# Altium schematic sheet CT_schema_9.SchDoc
size 278 x 170 mm
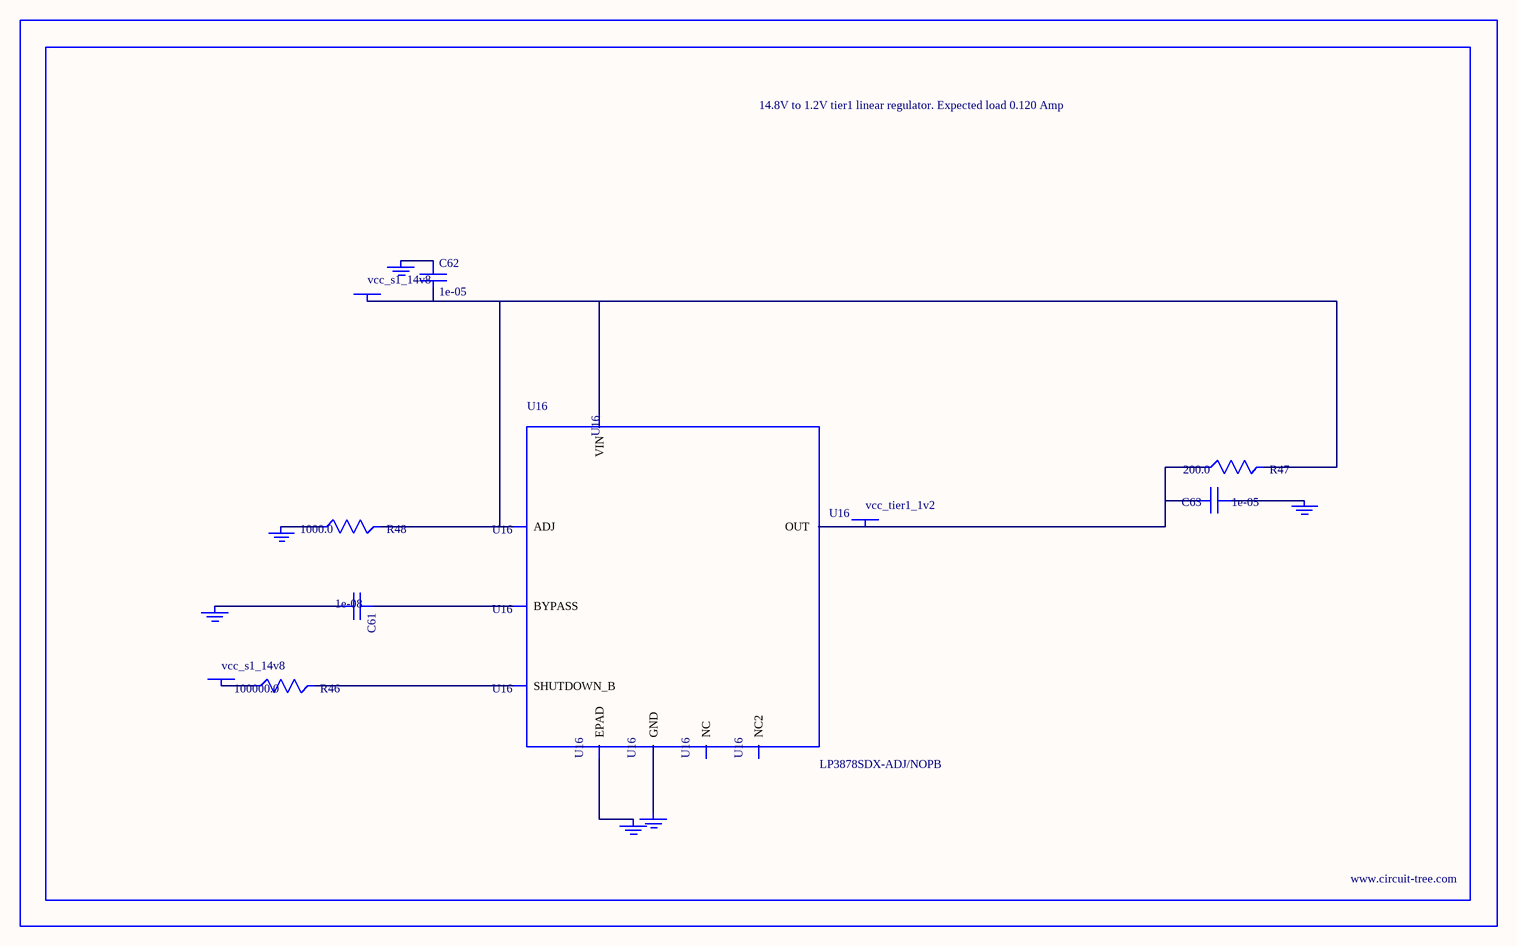
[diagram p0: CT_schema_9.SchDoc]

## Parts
BORDER8  (no value)
C61  1e-08  [C0402]
C62  1e-05  [C1210]
C63  1e-05  [C0805]
GND_INSTANCE_8_0  (no value)
GND_INSTANCE_8_1  (no value)
GND_INSTANCE_8_2  (no value)
GND_INSTANCE_8_3  (no value)
GND_INSTANCE_8_4  (no value)
GND_INSTANCE_8_5  (no value)
POWER_INSTANCE_8_0  vcc_s1_14v8
POWER_INSTANCE_8_1  vcc_s1_14v8
POWER_INSTANCE_8_2  vcc_tier1_1v2
R46  100000.0  [R0603]
R47  200.0  [R0603]
R48  1000.0  [R0603]
U16  LP3878SDX-ADJ/NOPB  [WSON-8]

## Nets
NetC61_1: C61.1 U16.1(BYPASS)
NetC61_2: C61.2 GND_INSTANCE_8_0.0(GND)
NetC62_1: C62.1 GND_INSTANCE_8_1.0(GND)
NetC62_2: C62.2 POWER_INSTANCE_8_0.0(PWR) R47.2 R48.2 U16.4(VIN) U16.6(ADJ)
NetC63_1: C63.1 GND_INSTANCE_8_2.0(GND)
NetC63_2: C63.2 POWER_INSTANCE_8_2.0(PWR) R47.1 U16.5(OUT)
NetGND_INSTANCE_8_3_0: GND_INSTANCE_8_3.0(GND) R48.1
NetGND_INSTANCE_8_4_0: GND_INSTANCE_8_4.0(GND) U16.PAD(EPAD)
NetGND_INSTANCE_8_5_0: GND_INSTANCE_8_5.0(GND) U16.3(GND)
NetPOWER_INSTANCE_8_1_0: POWER_INSTANCE_8_1.0(PWR) R46.1
NetR46_2: R46.2 U16.8(SHUTDOWN_B)

Not connected (* = marked no-connect by the designer): U16 2(NC) 7(NC2)

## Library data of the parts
BORDER8 = BORDER_PAGE8
C61 = C0402C103K3RAC
C62 = C1210C106K5PACTU
C63 = GRM219R60J106ME19D
GND_INSTANCE_8_0-GND_INSTANCE_8_5 = GND
POWER_INSTANCE_8_0-POWER_INSTANCE_8_2 = PWR
R46 = RC0603JR-07100KL
R47 = RC0603JR-07200RL
R48 = RC0603JR-071KL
